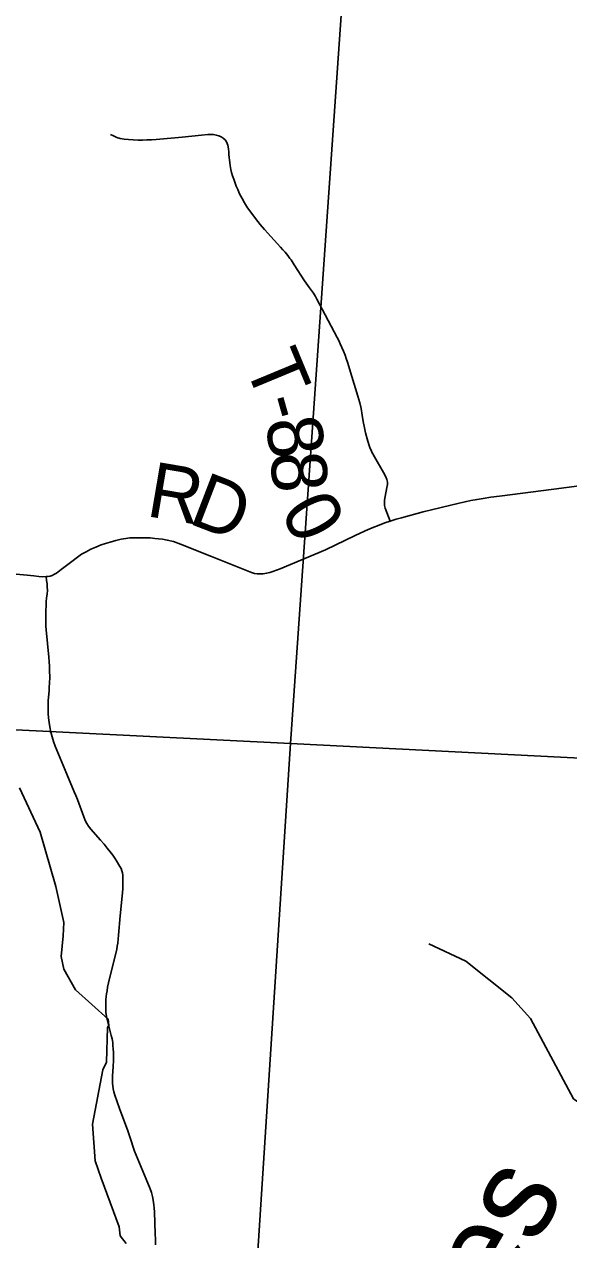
# Model space of a CAD drawing. Extents: x -2.1 to 31.9, y 6.3 to 28.3.
# Drawn here: x 3.259 to 3.819, y 24.409 to 25.658 of the extents above; entities that cross this region are included whole.
import ezdxf

# ---------------------------------------------------------------- set-up
doc = ezdxf.new("R2010")
doc.units = 0
for name, color, linetype in [('GM_X_County_Road', 7, 'Continuous'), ('GM_X_County_Road_Text', 7, 'Continuous'), ('GM_X_Minor_River', 7, 'Continuous'), ('GM_X_Minor_River_Text', 7, 'Continuous'), ('GM_X_Section', 7, 'Continuous'), ('GM_X_Township_Road', 7, 'Continuous'), ('GM_X_Township_Road_Text', 7, 'Continuous')]:
    doc.layers.add(name, color=color, linetype=linetype)

msp = doc.modelspace()

# ---------------------------------------------------------------- linework, layer by layer
at = {"layer": 'GM_X_County_Road'}
for points in [[(3.6088, 25.1368), (3.6097, 25.1372), (3.6167, 25.1402), (3.6239, 25.143), (3.6298, 25.1452), (3.6354, 25.1472), (3.6413, 25.149), (3.6471, 25.1506), (3.6694, 25.1565), (3.7063, 25.1656), (3.7124, 25.167), (3.7184, 25.1682), (3.7246, 25.1694), (3.7311, 25.1705), (3.7389, 25.1717), (3.7478, 25.1729), (3.8037, 25.1798), (3.8557, 25.1869), (3.8941, 25.1921), (3.9106, 25.1945), (3.9229, 25.1966), (3.93, 25.198), (3.9343, 25.1991)], [(3.2318, 25.0944), (3.2618, 25.0916), (3.2688, 25.0908), (3.274, 25.0902), (3.2781, 25.09), (3.2815, 25.0901), (3.2834, 25.0902), (3.2855, 25.0906), (3.2878, 25.0914), (3.29, 25.0925), (3.292, 25.0937), (3.294, 25.0951), (3.2982, 25.0983), (3.3078, 25.1055), (3.3138, 25.11), (3.318, 25.113), (3.3226, 25.1156), (3.3275, 25.1183), (3.3324, 25.1204), (3.3379, 25.1226), (3.3425, 25.1242), (3.3472, 25.1256), (3.3531, 25.1272), (3.3585, 25.1285), (3.3635, 25.1294), (3.3675, 25.1298), (3.3716, 25.13), (3.3756, 25.1301), (3.3795, 25.1301), (3.3844, 25.13), (3.3886, 25.1298), (3.3932, 25.1294), (3.397, 25.129), (3.401, 25.1285), (3.4061, 25.1277), (3.4125, 25.126), (3.4196, 25.1235), (3.4516, 25.1106), (3.4927, 25.0942), (3.4956, 25.0934), (3.4986, 25.093), (3.5014, 25.0928), (3.5048, 25.093), (3.5082, 25.0935), (3.5116, 25.0943), (3.5146, 25.0952), (3.5223, 25.098), (3.5687, 25.1175), (3.5993, 25.1324), (3.6088, 25.1368)], [(3.3941, 24.4035), (3.3938, 24.4093), (3.3936, 24.4147), (3.3929, 24.4373), (3.3926, 24.441), (3.3923, 24.4447), (3.3917, 24.4492), (3.3909, 24.4531), (3.3897, 24.4571), (3.3883, 24.461), (3.3843, 24.4709), (3.3725, 24.4996), (3.3706, 24.5049), (3.3691, 24.5092), (3.3655, 24.5206), (3.3569, 24.5435), (3.3522, 24.5574), (3.3512, 24.5606), (3.3503, 24.5639), (3.3499, 24.5668), (3.3497, 24.5694), (3.3497, 24.5719), (3.3498, 24.5769), (3.3504, 24.5866), (3.3507, 24.5929), (3.3507, 24.5975), (3.3506, 24.6012), (3.3505, 24.605), (3.3502, 24.6082), (3.3499, 24.6114), (3.3493, 24.6151), (3.3485, 24.6187), (3.344, 24.6363), (3.3433, 24.64), (3.343, 24.6427), (3.3428, 24.6459), (3.3428, 24.6489), (3.3429, 24.6522), (3.343, 24.6551), (3.3433, 24.6586), (3.3436, 24.6615), (3.3441, 24.6645), (3.3447, 24.6683), (3.3456, 24.6727), (3.354, 24.7074), (3.3546, 24.7105), (3.3551, 24.7136), (3.3556, 24.7174), (3.356, 24.7215), (3.3576, 24.7414), (3.3599, 24.7652), (3.3602, 24.7695), (3.3604, 24.7731), (3.3605, 24.7763), (3.3605, 24.779), (3.3604, 24.7814), (3.3602, 24.7834), (3.3599, 24.7856), (3.3593, 24.7877), (3.3585, 24.79), (3.3574, 24.7922), (3.3539, 24.7981), (3.3521, 24.8009), (3.35, 24.8038), (3.3474, 24.8074), (3.3443, 24.8112), (3.341, 24.8152), (3.3375, 24.8193), (3.3275, 24.8306), (3.3251, 24.8336), (3.3233, 24.8363), (3.3222, 24.8382), (3.3211, 24.8405), (3.3201, 24.8433), (3.3136, 24.8612), (3.3121, 24.8651), (3.3104, 24.8689), (3.3011, 24.8911), (3.2908, 24.9158), (3.289, 24.9207), (3.2877, 24.9253), (3.2864, 24.9302), (3.2852, 24.9356), (3.2845, 24.9402), (3.284, 24.945), (3.2836, 24.9495), (3.2835, 24.9537), (3.2835, 24.9579), (3.2837, 24.9628), (3.2845, 24.9726), (3.2847, 24.9764), (3.2849, 24.9805), (3.2851, 24.9867), (3.285, 24.9932), (3.2848, 24.9982), (3.2846, 25.0026), (3.2842, 25.0072), (3.2815, 25.0355), (3.2813, 25.0393), (3.2811, 25.0426), (3.2811, 25.0463), (3.2811, 25.05), (3.2812, 25.0554), (3.2814, 25.0601), (3.2816, 25.0641), (3.282, 25.0683), (3.2824, 25.072), (3.2827, 25.0761), (3.2826, 25.0794), (3.2824, 25.0826), (3.282, 25.086), (3.2815, 25.0901)]]:
    msp.add_lwpolyline(points, dxfattribs=at)
at = {"layer": 'GM_X_Minor_River'}
for points in [[(3.338, 24.472), (3.332, 24.4899), (3.3293, 24.5275), (3.3398, 24.5834), (3.3436, 24.591), (3.3447, 24.6267), (3.3458, 24.629), (3.3454, 24.6355), (3.3118, 24.6654), (3.2996, 24.6867), (3.297, 24.6996), (3.2989, 24.7209), (3.2996, 24.7346), (3.2916, 24.7718), (3.2753, 24.8276), (3.2541, 24.8732)], [(3.8889, 24.5175), (3.8695, 24.523), (3.8238, 24.5535), (3.7796, 24.636), (3.7605, 24.6572), (3.7132, 24.6949), (3.6752, 24.7126)], [(3.3638, 24.4048), (3.3577, 24.4128), (3.3566, 24.4219), (3.338, 24.472)]]:
    msp.add_lwpolyline(points, dxfattribs=at)
at = {"layer": 'GM_X_Section'}
for points in [[(2.5466, 25.9887), (3.6038, 25.9379), (3.5328, 24.9185), (2.4786, 24.9709)], [(3.6038, 25.9379), (4.6345, 25.8828), (4.5692, 24.8661), (3.5328, 24.9185)], [(2.4786, 24.9709), (3.5328, 24.9185), (3.4671, 23.8965), (2.4194, 23.947)], [(3.5328, 24.9185), (4.5692, 24.8661), (4.5062, 23.8498), (3.4671, 23.8965)]]:
    msp.add_lwpolyline(points, close=True, dxfattribs=at)
at = {"layer": 'GM_X_Township_Road'}
for points in [[(3.6166, 25.218), (3.6161, 25.219), (3.6145, 25.2226), (3.6134, 25.2258), (3.6116, 25.2317), (3.61, 25.2377), (3.6089, 25.2429), (3.6076, 25.2496), (3.6066, 25.2561), (3.6054, 25.2628), (3.6041, 25.2686), (3.6019, 25.2755), (3.5957, 25.2957), (3.5914, 25.3103), (3.5901, 25.3143), (3.5889, 25.3175), (3.5873, 25.3216), (3.5857, 25.3256), (3.584, 25.3294), (3.5824, 25.3328), (3.5808, 25.3358), (3.5686, 25.3591), (3.5599, 25.3752), (3.5584, 25.3779), (3.5564, 25.3812), (3.5545, 25.384), (3.5524, 25.3869), (3.5471, 25.394), (3.5365, 25.4105), (3.5355, 25.4122), (3.5345, 25.4138), (3.5333, 25.4156), (3.5322, 25.4171), (3.53, 25.42), (3.5272, 25.4234), (3.5249, 25.4258), (3.5224, 25.4285), (3.506, 25.4467), (3.5015, 25.4519), (3.4968, 25.4581), (3.4919, 25.4646), (3.4886, 25.4692), (3.4856, 25.4741), (3.4831, 25.4785), (3.4805, 25.4835), (3.4785, 25.4878), (3.477, 25.4914), (3.4755, 25.4953), (3.4744, 25.4984), (3.4732, 25.502), (3.4722, 25.5055), (3.4715, 25.5084), (3.4708, 25.5125), (3.4703, 25.5154), (3.47, 25.5182), (3.4698, 25.5204), (3.4695, 25.5243), (3.4694, 25.5267), (3.4691, 25.5292), (3.4687, 25.5316), (3.4683, 25.5335), (3.4678, 25.5352), (3.4669, 25.5368), (3.4656, 25.5388), (3.4637, 25.5406), (3.4616, 25.5419), (3.4592, 25.543), (3.4565, 25.5438), (3.4537, 25.5443), (3.4509, 25.5444), (3.4478, 25.5443), (3.4414, 25.5437), (3.4215, 25.5415), (3.3947, 25.5392), (3.3897, 25.539), (3.3851, 25.5388), (3.3804, 25.5387), (3.376, 25.5387), (3.3708, 25.5388), (3.366, 25.5391), (3.3618, 25.5395), (3.3577, 25.5404), (3.3542, 25.5414), (3.3508, 25.5429), (3.3478, 25.5444)], [(3.6354, 25.1472), (3.6302, 25.1604), (3.6296, 25.163), (3.6293, 25.1662), (3.6294, 25.1687), (3.63, 25.1725), (3.632, 25.1816), (3.6324, 25.1846), (3.6325, 25.187), (3.6319, 25.1898), (3.6309, 25.1926), (3.6285, 25.1969), (3.6191, 25.213), (3.6175, 25.2161), (3.6166, 25.218)]]:
    msp.add_lwpolyline(points, dxfattribs=at)

# ---------------------------------------------------------------- texts
at = {"layer": 'GM_X_County_Road_Text'}
for s, rotation, p in [('R', 350.3214, (3.3832, 25.1525)), ('D', 338.9366, (3.4263, 25.1454))]:
    msp.add_text(s, height=0.0568, rotation=rotation, dxfattribs=at).set_placement(p)
at = {"layer": 'GM_X_Minor_River_Text'}
msp.add_text('Drakes', height=0.09469, rotation=59.9948, dxfattribs=at).set_placement((3.6153, 24.1097))
at = {"layer": 'GM_X_Township_Road_Text'}
for s, rotation, p in [('T', 292.5216, (3.4847, 25.3086)), ('-', 285.7953, (3.5004, 25.271)), ('8', 279.6839, (3.5064, 25.2501)), ('8', 274.0676, (3.5121, 25.217)), ('0', 297.5303, (3.5214, 25.1579))]:
    msp.add_text(s, height=0.0568, rotation=rotation, dxfattribs=at).set_placement(p)

doc.saveas('drawing.dxf')
